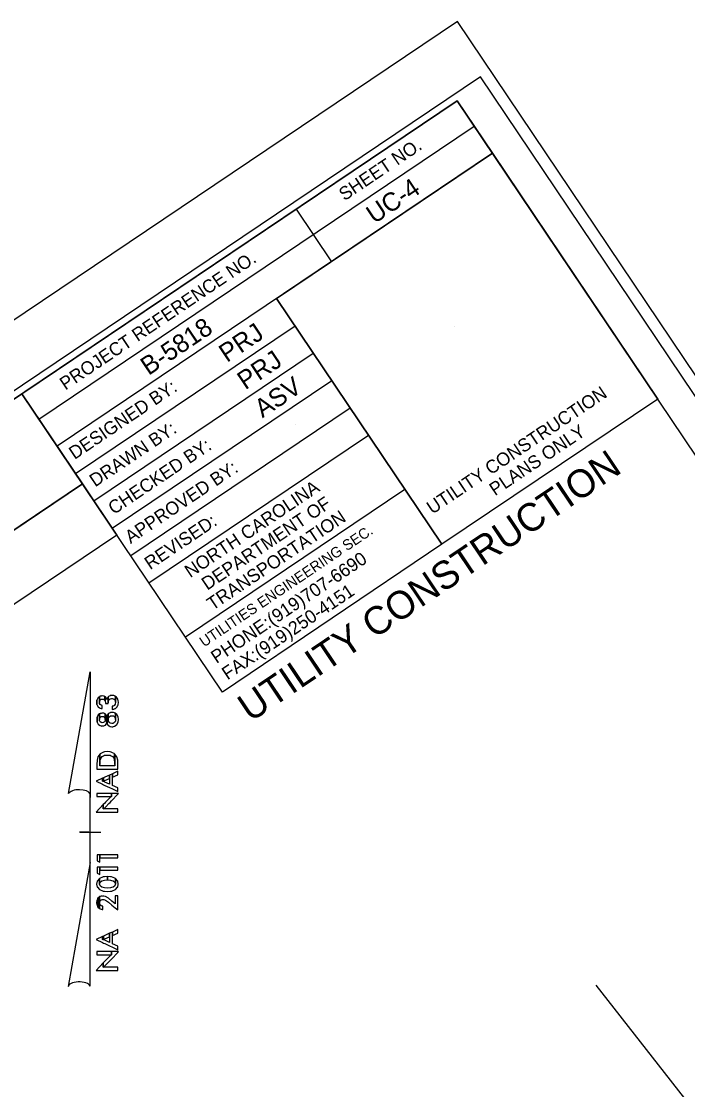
# Model space of a CAD drawing. Extents: x 1439200 to 1640973, y 392611 to 606444.
# Drawn here: x 1640660.5 to 1640762, y 393189.2 to 393351.9 of the extents above; entities that cross this region are included whole.
import ezdxf

# ---------------------------------------------------------------- set-up
doc = ezdxf.new("R2010")
doc.units = 0
for name, color, linetype in [('Matchline', 7, 'Continuous'), ('North Arrow NAD83 CELL', 7, 'Continuous'), ('Old_Level_60', 7, 'Continuous'), ('Sheet Data Field CELL', 7, 'Continuous'), ('Sheet Plot Border Inside CELL', 7, 'Continuous'), ('Sheet Plot Border Outside CELL', 7, 'Continuous'), ('Sheet Sticker Exception Certification CELL', 7, 'Continuous'), ('UC Plan Sheet 34 CELL', 7, 'Continuous')]:
    doc.layers.add(name, color=color, linetype=linetype)

msp = doc.modelspace()

# ---------------------------------------------------------------- linework, layer by layer
at = {"layer": 'Matchline'}
msp.add_line((1640747.99, 393205.15), (1640883.51, 393032.48), dxfattribs=at)
at = {"layer": 'North Arrow NAD83 CELL'}
for p, q in [((1640667.65, 393234.34), (1640670.94, 393252.88)), ((1640670.96, 393252.88), (1640670.94, 393252.88)), ((1640670.96, 393252.88), (1640670.94, 393252.88)), ((1640670.96, 393252.88), (1640670.95, 393233.76)), ((1640670.94, 393223.84), (1640670.95, 393234.32)), ((1640670.95, 393233.76), (1640670.95, 393234.3)), ((1640669.35, 393228.48), (1640669.33, 393228.48)), ((1640670.77, 393228.48), (1640669.35, 393228.48)), ((1640669.37, 393228.48), (1640672.57, 393228.48)), ((1640670.94, 393223.84), (1640667.6, 393204.94)), ((1640670.96, 393205.02), (1640670.94, 393223.84))]:
    msp.add_line(p, q, dxfattribs=at)
for points in [[(1640671.94, 393248.27), (1640671.98, 393247.9), (1640671.98, 393248.56)], [(1640672.74, 393247.29), (1640672.78, 393247.28), (1640672.78, 393247.75), (1640672.74, 393247.76), (1640672.63, 393247.78), (1640672.61, 393247.79), (1640672.61, 393247.79), (1640672.47, 393247.88), (1640672.47, 393247.89), (1640672.46, 393247.91), (1640672.39, 393248.03), (1640672.38, 393248.11), (1640672.37, 393248.14), (1640672.36, 393248.23), (1640672.36, 393249.09), (1640672.18, 393248.98), (1640672.14, 393248.89), (1640672.14, 393248.89), (1640672, 393248.65), (1640671.98, 393248.56), (1640671.98, 393247.9), (1640672, 393247.87), (1640672.14, 393247.59), (1640672.18, 393247.55), (1640672.36, 393247.4), (1640672.37, 393247.39), (1640672.38, 393247.39), (1640672.39, 393247.38), (1640672.46, 393247.36), (1640672.47, 393247.36), (1640672.47, 393247.35), (1640672.61, 393247.3), (1640672.61, 393247.3), (1640672.63, 393247.3)], [(1640673.1, 393248.62), (1640673.16, 393248.58), (1640673.16, 393249.12), (1640673.1, 393249.16), (1640673, 393249.18), (1640672.8, 393249.22), (1640672.79, 393249.22), (1640672.78, 393249.22), (1640672.74, 393249.21), (1640672.63, 393249.19), (1640672.61, 393249.19), (1640672.61, 393249.19), (1640672.61, 393249.19), (1640672.47, 393249.17), (1640672.47, 393249.16), (1640672.46, 393249.16), (1640672.39, 393249.12), (1640672.38, 393249.11), (1640672.37, 393249.1), (1640672.36, 393249.09), (1640672.36, 393248.23), (1640672.37, 393248.38), (1640672.38, 393248.42), (1640672.39, 393248.45), (1640672.46, 393248.57), (1640672.47, 393248.59), (1640672.47, 393248.59), (1640672.61, 393248.69), (1640672.61, 393248.69), (1640672.63, 393248.7), (1640672.74, 393248.72), (1640672.78, 393248.73), (1640672.79, 393248.73), (1640672.8, 393248.73), (1640673, 393248.69)], [(1640673.16, 393248.58), (1640673.24, 393248.41), (1640673.24, 393249.07), (1640673.16, 393249.12)], [(1640673.56, 393248.07), (1640673.68, 393248.07), (1640673.68, 393249.04), (1640673.55, 393248.87), (1640673.5, 393248.67), (1640673.45, 393248.82), (1640673.34, 393249.01), (1640673.27, 393249.06), (1640673.26, 393249.06), (1640673.24, 393249.07), (1640673.24, 393248.41), (1640673.26, 393248.22), (1640673.27, 393248.07), (1640673.34, 393248.07), (1640673.46, 393248.07), (1640673.5, 393248.07)], [(1640674.78, 393248.43), (1640674.81, 393248.26), (1640674.81, 393249.12), (1640674.78, 393249.14), (1640674.76, 393249.15), (1640674.76, 393249.15), (1640674.65, 393249.23), (1640674.64, 393249.23), (1640674.63, 393249.23), (1640674.55, 393249.25), (1640674.45, 393249.26), (1640674.44, 393249.27), (1640674.32, 393249.29), (1640674.22, 393249.28), (1640674.02, 393249.25), (1640673.99, 393249.24), (1640673.85, 393249.17), (1640673.74, 393249.11), (1640673.73, 393249.1), (1640673.69, 393249.05), (1640673.68, 393249.04), (1640673.68, 393248.17), (1640673.69, 393248.32), (1640673.73, 393248.49), (1640673.74, 393248.52), (1640673.85, 393248.68), (1640673.99, 393248.76), (1640674.02, 393248.78), (1640674.22, 393248.81), (1640674.32, 393248.8), (1640674.44, 393248.79), (1640674.45, 393248.78), (1640674.55, 393248.73), (1640674.63, 393248.69), (1640674.64, 393248.68), (1640674.65, 393248.66), (1640674.76, 393248.51)], [(1640675.2, 393247.87), (1640675.24, 393248.27), (1640675.2, 393248.46), (1640675.16, 393248.7), (1640675.05, 393248.88), (1640674.96, 393249.03), (1640674.82, 393249.12), (1640674.81, 393249.12), (1640674.81, 393248.26), (1640674.78, 393247.97), (1640674.76, 393247.95), (1640674.65, 393247.79), (1640674.64, 393247.76), (1640674.63, 393247.76), (1640674.55, 393247.72), (1640674.45, 393247.66), (1640674.44, 393247.66), (1640674.32, 393247.65), (1640674.31, 393247.65), (1640674.31, 393247.15), (1640674.32, 393247.16), (1640674.44, 393247.17), (1640674.45, 393247.17), (1640674.55, 393247.19), (1640674.63, 393247.22), (1640674.64, 393247.22), (1640674.65, 393247.23), (1640674.77, 393247.28), (1640674.78, 393247.28), (1640674.81, 393247.3), (1640674.82, 393247.3), (1640674.96, 393247.45), (1640675.05, 393247.54), (1640675.16, 393247.78)], [(1640673.39, 393244.92), (1640673.48, 393245.08), (1640673.48, 393246.13), (1640673.39, 393246.3), (1640673.39, 393246.3), (1640673.26, 393246.44), (1640673.26, 393246.44), (1640673.23, 393246.46), (1640673.23, 393245.6), (1640673.21, 393245.4), (1640673.11, 393245.25), (1640673.05, 393245.2), (1640673.05, 393245.2), (1640673.04, 393245.2), (1640672.97, 393245.16), (1640672.8, 393245.12), (1640672.74, 393245.14), (1640672.62, 393245.16), (1640672.47, 393245.27), (1640672.47, 393245.27), (1640672.42, 393245.35), (1640672.39, 393245.42), (1640672.36, 393245.61), (1640672.36, 393246.46), (1640672.17, 393246.31), (1640672, 393245.99), (1640672, 393245.22), (1640672.17, 393244.89), (1640672.36, 393244.75), (1640672.39, 393244.73), (1640672.42, 393244.7), (1640672.47, 393244.69), (1640672.47, 393244.69), (1640672.62, 393244.65), (1640672.74, 393244.62), (1640672.8, 393244.63), (1640672.97, 393244.65), (1640673.04, 393244.66), (1640673.05, 393244.66), (1640673.11, 393244.69), (1640673.21, 393244.74), (1640673.23, 393244.75), (1640673.26, 393244.77), (1640673.26, 393244.77), (1640673.39, 393244.92)], [(1640673.2, 393245.81), (1640673.23, 393245.6), (1640673.23, 393246.46), (1640673.2, 393246.47), (1640673.11, 393246.52), (1640673.05, 393246.56), (1640673.04, 393246.56), (1640672.97, 393246.56), (1640672.8, 393246.58), (1640672.8, 393246.58), (1640672.74, 393246.59), (1640672.62, 393246.55), (1640672.47, 393246.52), (1640672.47, 393246.51), (1640672.42, 393246.5), (1640672.39, 393246.47), (1640672.36, 393246.46), (1640672.36, 393245.61), (1640672.39, 393245.79), (1640672.42, 393245.86), (1640672.47, 393245.95), (1640672.47, 393245.95), (1640672.62, 393246.05), (1640672.74, 393246.07), (1640672.8, 393246.08), (1640672.97, 393246.05), (1640673.04, 393246.01), (1640673.05, 393246), (1640673.11, 393245.96)], [(1640675.19, 393245.21), (1640675.24, 393245.6), (1640675.19, 393246.01), (1640675.19, 393246.01), (1640675.03, 393246.36), (1640675.03, 393246.37), (1640674.82, 393246.53), (1640674.82, 393245.6), (1640674.79, 393245.36), (1640674.73, 393245.27), (1640674.73, 393245.26), (1640674.67, 393245.16), (1640674.49, 393245.05), (1640674.38, 393245.03), (1640674.37, 393245.03), (1640674.27, 393245.01), (1640674.04, 393245.05), (1640674.01, 393245.07), (1640673.85, 393245.19), (1640673.85, 393245.19), (1640673.74, 393245.38), (1640673.73, 393245.48), (1640673.72, 393245.54), (1640673.71, 393245.6), (1640673.71, 393246.49), (1640673.55, 393246.3), (1640673.55, 393244.91), (1640673.71, 393244.72), (1640673.72, 393244.71), (1640673.73, 393244.7), (1640673.74, 393244.69), (1640673.85, 393244.64), (1640673.85, 393244.64), (1640674.01, 393244.56), (1640674.04, 393244.55), (1640674.27, 393244.52), (1640674.37, 393244.51), (1640674.38, 393244.51), (1640674.49, 393244.54), (1640674.67, 393244.59), (1640674.73, 393244.61), (1640674.79, 393244.65), (1640674.82, 393244.68), (1640675.03, 393244.84), (1640675.03, 393244.85), (1640675.19, 393245.2)], [(1640674.79, 393245.85), (1640674.82, 393245.6), (1640674.82, 393246.53), (1640674.79, 393246.56), (1640674.73, 393246.6), (1640674.67, 393246.62), (1640674.49, 393246.66), (1640674.38, 393246.69), (1640674.37, 393246.7), (1640674.27, 393246.68), (1640674.27, 393246.68), (1640674.04, 393246.66), (1640674.01, 393246.65), (1640673.85, 393246.57), (1640673.85, 393246.56), (1640673.74, 393246.51), (1640673.72, 393246.5), (1640673.72, 393246.5), (1640673.71, 393246.49), (1640673.71, 393245.6), (1640673.72, 393245.67), (1640673.73, 393245.73), (1640673.74, 393245.83), (1640673.85, 393246.02), (1640673.85, 393246.02), (1640674.01, 393246.14), (1640674.04, 393246.16), (1640674.27, 393246.2), (1640674.37, 393246.18), (1640674.38, 393246.18), (1640674.49, 393246.16), (1640674.67, 393246.04), (1640674.73, 393245.94)], [(1640671.99, 393245.25), (1640672, 393245.22), (1640672, 393245.99), (1640671.99, 393245.99), (1640671.94, 393245.6), (1640671.94, 393245.6)], [(1640673.55, 393244.92), (1640673.55, 393244.91), (1640673.55, 393246.3), (1640673.54, 393246.29), (1640673.48, 393246.13), (1640673.48, 393245.08)], [(1640675.15, 393238.05), (1640675.16, 393238.05), (1640675.16, 393238.74), (1640675.15, 393239.4), (1640675.01, 393239.95), (1640674.69, 393240.35), (1640674.69, 393238.56), (1640674.68, 393238.56), (1640674.66, 393238.56), (1640674.59, 393238.56), (1640674.34, 393238.56), (1640674.16, 393238.56), (1640673.98, 393238.56), (1640673.57, 393238.56), (1640673.57, 393238.56), (1640673.15, 393238.56), (1640672.98, 393238.56), (1640672.79, 393238.56), (1640672.55, 393238.56), (1640672.48, 393238.56), (1640672.45, 393238.56), (1640672.44, 393238.56), (1640672.44, 393240.34), (1640672.13, 393239.95), (1640671.99, 393239.4), (1640671.98, 393238.74), (1640671.98, 393238.04), (1640671.99, 393238.04), (1640672.13, 393238.04), (1640672.44, 393238.04), (1640672.45, 393238.04), (1640672.48, 393238.04), (1640672.55, 393238.04), (1640672.79, 393238.04), (1640672.98, 393238.04), (1640673.15, 393238.04), (1640673.57, 393238.04), (1640673.57, 393238.04), (1640673.98, 393238.04), (1640674.16, 393238.04), (1640674.34, 393238.04), (1640674.59, 393238.04), (1640674.66, 393238.04), (1640674.68, 393238.04), (1640674.69, 393238.04), (1640675.01, 393238.05)], [(1640674.66, 393239.41), (1640674.68, 393239.34), (1640674.68, 393240.37), (1640674.66, 393240.39), (1640674.58, 393240.43), (1640674.34, 393240.56), (1640674.16, 393240.66), (1640673.98, 393240.69), (1640673.98, 393240.69), (1640673.57, 393240.74), (1640673.57, 393240.74), (1640673.15, 393240.69), (1640672.98, 393240.66), (1640672.79, 393240.56), (1640672.55, 393240.43), (1640672.48, 393240.39), (1640672.45, 393240.36), (1640672.44, 393240.34), (1640672.44, 393238.75), (1640672.45, 393239.34), (1640672.48, 393239.43), (1640672.55, 393239.69), (1640672.79, 393239.98), (1640672.98, 393240.07), (1640673.15, 393240.16), (1640673.57, 393240.21), (1640673.57, 393240.21), (1640673.98, 393240.16), (1640674.16, 393240.07), (1640674.34, 393239.98), (1640674.58, 393239.69)], [(1640674.68, 393239.34), (1640674.69, 393238.75), (1640674.69, 393240.35), (1640674.68, 393240.37)], [(1640674.34, 393235.05), (1640675.16, 393234.67), (1640675.16, 393235.21), (1640674.34, 393235.58), (1640674.34, 393237.36), (1640673.91, 393237.16), (1640673.91, 393235.77), (1640673.19, 393236.09), (1640673.18, 393236.1), (1640673, 393236.16), (1640673, 393236.16), (1640672.82, 393236.21), (1640672.82, 393236.66), (1640671.85, 393236.2), (1640672.82, 393235.75), (1640673, 393235.67), (1640673, 393235.67), (1640673.18, 393235.59), (1640673.19, 393235.58), (1640673.91, 393235.25)], [(1640672.82, 393236.21), (1640673, 393236.26), (1640673, 393236.74), (1640672.82, 393236.66)], [(1640673.19, 393236.33), (1640673.91, 393236.65), (1640673.91, 393237.16), (1640673.18, 393236.82), (1640673.18, 393236.82), (1640673, 393236.74), (1640673, 393236.74), (1640673, 393236.26), (1640673, 393236.26), (1640673.18, 393236.33)], [(1640674.34, 393236.84), (1640675.16, 393237.2), (1640675.16, 393237.75), (1640674.34, 393237.36)], [(1640673.98, 393233.89), (1640674.19, 393233.89), (1640674.19, 393234.37), (1640673.98, 393234.37), (1640673.8, 393234.37), (1640673.3, 393234.37), (1640673.11, 393234.37), (1640671.98, 393234.36), (1640671.98, 393233.89), (1640673.11, 393233.89), (1640673.3, 393233.89), (1640673.8, 393233.89)], [(1640675.16, 393234.24), (1640675.29, 393234.37), (1640675.16, 393234.37), (1640674.19, 393234.37), (1640674.19, 393233.89), (1640673.98, 393233.72), (1640673.8, 393233.54), (1640673.3, 393233.03), (1640673.11, 393232.83), (1640672.95, 393232.66), (1640672.95, 393232), (1640673.11, 393232.12), (1640673.31, 393232.3), (1640673.8, 393232.82), (1640673.98, 393233), (1640674.19, 393233.22)], [(1640674.19, 393231.52), (1640675.16, 393231.52), (1640675.16, 393232), (1640674.19, 393232), (1640673.98, 393232), (1640673.8, 393232), (1640673.31, 393232), (1640673.11, 393232), (1640672.95, 393232), (1640672.95, 393232.66), (1640671.86, 393231.52), (1640672.95, 393231.52), (1640673.12, 393231.52), (1640673.31, 393231.52), (1640673.8, 393231.52), (1640673.98, 393231.52)], [(1640671.99, 393224.08), (1640672.41, 393223.88), (1640672.41, 393225.01), (1640671.99, 393225.01)], [(1640672.41, 393224.53), (1640675.15, 393224.53), (1640675.15, 393225.01), (1640672.41, 393225.01)], [(1640671.99, 393222.2), (1640672.41, 393222), (1640672.41, 393223.13), (1640671.99, 393223.13)], [(1640672.41, 393222.66), (1640675.15, 393222.66), (1640675.15, 393223.13), (1640672.41, 393223.13)], [(1640675.14, 393220.1), (1640675.23, 393220.55), (1640675.14, 393220.99), (1640675.13, 393221.02), (1640674.79, 393221.39), (1640674.79, 393220.54), (1640674.78, 393220.52), (1640674.78, 393220.51), (1640674.71, 393220.27), (1640674.46, 393220.07), (1640674.45, 393220.07), (1640674.45, 393220.07), (1640674.22, 393220.01), (1640674.22, 393220.01), (1640674.06, 393219.96), (1640674.05, 393219.96), (1640673.59, 393219.92), (1640673.58, 393219.92), (1640673.58, 393219.92), (1640673.12, 393219.96), (1640672.95, 393220.01), (1640672.94, 393220.01), (1640672.72, 393220.07), (1640672.71, 393220.07), (1640672.45, 393220.27), (1640672.38, 393220.53), (1640672.38, 393220.54), (1640672.38, 393220.56), (1640672.38, 393221.4), (1640672.04, 393221.03), (1640672.03, 393221.01), (1640671.93, 393220.55), (1640671.93, 393220.55), (1640672.03, 393220.08), (1640672.04, 393220.08), (1640672.38, 393219.71), (1640672.38, 393219.7), (1640672.38, 393219.7), (1640672.45, 393219.68), (1640672.71, 393219.57), (1640672.72, 393219.57), (1640672.94, 393219.47), (1640672.95, 393219.47), (1640673.12, 393219.46), (1640673.58, 393219.41), (1640673.58, 393219.41), (1640673.59, 393219.41), (1640674.05, 393219.45), (1640674.06, 393219.45), (1640674.22, 393219.47), (1640674.23, 393219.47), (1640674.45, 393219.57), (1640674.46, 393219.57), (1640674.71, 393219.67), (1640674.78, 393219.7), (1640674.78, 393219.7), (1640674.79, 393219.71), (1640675.13, 393220.09)], [(1640673.12, 393221.14), (1640673.58, 393221.18), (1640673.58, 393221.69), (1640673.12, 393221.65), (1640672.94, 393221.63), (1640672.94, 393221.63), (1640672.94, 393221.63), (1640672.72, 393221.54), (1640672.72, 393221.54), (1640672.71, 393221.54), (1640672.45, 393221.43), (1640672.45, 393221.43), (1640672.38, 393221.41), (1640672.38, 393221.4), (1640672.38, 393221.4), (1640672.38, 393220.56), (1640672.38, 393220.58), (1640672.38, 393220.59), (1640672.45, 393220.83), (1640672.71, 393221.03), (1640672.72, 393221.03), (1640672.94, 393221.09), (1640672.94, 393221.09)], [(1640674.78, 393220.57), (1640674.79, 393220.54), (1640674.79, 393221.39), (1640674.78, 393221.4), (1640674.78, 393221.4), (1640674.71, 393221.43), (1640674.46, 393221.53), (1640674.45, 393221.54), (1640674.22, 393221.63), (1640674.22, 393221.63), (1640674.06, 393221.65), (1640674.04, 393221.65), (1640673.59, 393221.69), (1640673.58, 393221.69), (1640673.58, 393221.69), (1640673.58, 393221.18), (1640673.58, 393221.18), (1640673.59, 393221.18), (1640674.05, 393221.14), (1640674.06, 393221.14), (1640674.22, 393221.1), (1640674.22, 393221.1), (1640674.45, 393221.03), (1640674.46, 393221.03), (1640674.71, 393220.83), (1640674.78, 393220.58)], [(1640672.12, 393217.06), (1640672.13, 393217.05), (1640672.13, 393218.41), (1640672.12, 393218.41), (1640671.99, 393218.11), (1640671.97, 393218.07), (1640671.93, 393217.7), (1640671.93, 393217.7), (1640671.97, 393217.45), (1640671.99, 393217.34)], [(1640672.13, 393217.05), (1640672.36, 393216.83), (1640672.36, 393218.61), (1640672.13, 393218.41)], [(1640672.82, 393216.69), (1640672.87, 393216.69), (1640672.87, 393217.18), (1640672.82, 393217.19), (1640672.79, 393217.19), (1640672.79, 393217.19), (1640672.65, 393217.24), (1640672.63, 393217.25), (1640672.61, 393217.27), (1640672.49, 393217.36), (1640672.46, 393217.42), (1640672.4, 393217.54), (1640672.4, 393217.56), (1640672.39, 393217.8), (1640672.39, 393218.64), (1640672.36, 393218.61), (1640672.36, 393216.83), (1640672.39, 393216.82), (1640672.4, 393216.81), (1640672.4, 393216.81), (1640672.46, 393216.78), (1640672.49, 393216.77), (1640672.61, 393216.72), (1640672.63, 393216.71), (1640672.65, 393216.71), (1640672.79, 393216.7), (1640672.79, 393216.69)], [(1640674.74, 393216.95), (1640675.15, 393216.61), (1640675.15, 393218.74), (1640674.74, 393218.74), (1640674.74, 393217.53), (1640674.27, 393217.94), (1640673.72, 393218.38), (1640673.72, 393218.39), (1640673.29, 393218.64), (1640673.29, 393218.64), (1640673.28, 393218.65), (1640673.01, 393218.7), (1640672.87, 393218.73), (1640672.82, 393218.74), (1640672.79, 393218.73), (1640672.79, 393218.73), (1640672.65, 393218.7), (1640672.63, 393218.7), (1640672.61, 393218.69), (1640672.49, 393218.67), (1640672.49, 393218.67), (1640672.46, 393218.66), (1640672.4, 393218.65), (1640672.4, 393218.65), (1640672.39, 393218.64), (1640672.39, 393217.8), (1640672.4, 393217.83), (1640672.4, 393217.85), (1640672.46, 393218.02), (1640672.49, 393218.05), (1640672.61, 393218.16), (1640672.63, 393218.17), (1640672.65, 393218.17), (1640672.79, 393218.22), (1640672.79, 393218.22), (1640672.82, 393218.22), (1640672.87, 393218.22), (1640673.01, 393218.21), (1640673.28, 393218.11), (1640673.29, 393218.1), (1640673.72, 393217.8), (1640673.72, 393217.8), (1640674.27, 393217.34)], [(1640674.33, 393210.94), (1640675.15, 393210.56), (1640675.15, 393211.1), (1640674.33, 393211.47), (1640674.33, 393213.25), (1640673.9, 393213.05), (1640673.9, 393211.66), (1640673.18, 393211.99), (1640673.17, 393211.99), (1640672.99, 393212.05), (1640672.99, 393212.05), (1640672.81, 393212.1), (1640672.81, 393212.55), (1640671.84, 393212.1), (1640672.81, 393211.64), (1640672.99, 393211.56), (1640672.99, 393211.56), (1640673.17, 393211.48), (1640673.18, 393211.48), (1640673.9, 393211.14)], [(1640672.81, 393212.1), (1640672.99, 393212.15), (1640672.99, 393212.63), (1640672.81, 393212.55)], [(1640673.18, 393212.22), (1640673.9, 393212.54), (1640673.9, 393213.05), (1640673.17, 393212.72), (1640673.17, 393212.72), (1640672.99, 393212.63), (1640672.99, 393212.63), (1640672.99, 393212.15), (1640672.99, 393212.16), (1640673.17, 393212.22)], [(1640674.33, 393212.73), (1640675.15, 393213.09), (1640675.15, 393213.64), (1640674.33, 393213.25)], [(1640673.97, 393209.78), (1640674.18, 393209.78), (1640674.18, 393210.26), (1640673.97, 393210.26), (1640673.79, 393210.26), (1640673.29, 393210.26), (1640673.1, 393210.26), (1640671.97, 393210.26), (1640671.97, 393209.78), (1640673.1, 393209.78), (1640673.29, 393209.78), (1640673.79, 393209.78)], [(1640675.15, 393210.13), (1640675.28, 393210.26), (1640675.15, 393210.26), (1640674.18, 393210.26), (1640674.18, 393209.78), (1640673.97, 393209.61), (1640673.79, 393209.43), (1640673.3, 393208.92), (1640673.1, 393208.72), (1640672.94, 393208.55), (1640672.94, 393207.89), (1640673.1, 393208.01), (1640673.3, 393208.19), (1640673.79, 393208.71), (1640673.97, 393208.9), (1640674.18, 393209.11)], [(1640674.18, 393207.41), (1640675.15, 393207.41), (1640675.15, 393207.89), (1640674.18, 393207.89), (1640673.97, 393207.89), (1640673.79, 393207.89), (1640673.3, 393207.89), (1640673.1, 393207.89), (1640672.94, 393207.89), (1640672.94, 393208.55), (1640671.85, 393207.41), (1640672.94, 393207.41), (1640673.11, 393207.41), (1640673.3, 393207.41), (1640673.79, 393207.41), (1640673.97, 393207.41)]]:
    msp.add_lwpolyline(points, close=True, dxfattribs=at)
for centre, start_param, end_param in [((1640669.3, 393234.14), 0.216388, 2.908219), ((1640669.29, 393204.87), 0.201328, 3.141593)]:
    msp.add_ellipse(centre, major_axis=(1.69, -0.01), ratio=0.461098, start_param=start_param, end_param=end_param, dxfattribs=at)
at = {"layer": 'Old_Level_60'}
msp.add_lwpolyline([(1640594.15, 393250.57), (1640660.54, 393295.23), (1640669.78, 393281.5), (1640603.39, 393236.83)], close=True, dxfattribs=at)
at = {"layer": 'Sheet Plot Border Inside CELL'}
msp.add_lwpolyline([(1640730.44, 393343.49), (1640177.37, 392971.37), (1640412.97, 392621.21), (1640966.04, 392993.34)], close=True, dxfattribs=at)
at = {"layer": 'Sheet Plot Border Outside CELL'}
msp.add_lwpolyline([(1640726.92, 393351.95), (1640168.05, 392975.92), (1640413.67, 392610.86), (1640972.54, 392986.89)], close=True, dxfattribs=at)
at = {"layer": 'Sheet Sticker Exception Certification CELL'}
for p, q in [((1640603.39, 393236.83), (1640669.78, 393281.5)), ((1640669.78, 393281.49), (1640675.03, 393273.7)), ((1640675.03, 393273.7), (1640608.64, 393229.03))]:
    msp.add_line(p, q, dxfattribs=at)
at = {"layer": 'UC Plan Sheet 34 CELL'}
for p, q in [((1640663.13, 393291.38), (1640729.45, 393336.01)), ((1640718.55, 393325.66), (1640718.55, 393325.66)), ((1640702.33, 393323.35), (1640707.71, 393315.34)), ((1640668.72, 393283.07), (1640702.16, 393305.56)), ((1640726.45, 393305.53), (1640726.45, 393305.53)), ((1640685.41, 393303.37), (1640685.41, 393303.37)), ((1640693.91, 393303.03), (1640693.91, 393303.03)), ((1640671.52, 393278.91), (1640704.95, 393301.4)), ((1640696.71, 393298.87), (1640696.71, 393298.87)), ((1640674.32, 393274.75), (1640707.75, 393297.25)), ((1640699.5, 393294.72), (1640699.5, 393294.72)), ((1640677.12, 393270.6), (1640710.55, 393293.09)), ((1640702.3, 393290.56), (1640702.3, 393290.56)), ((1640679.91, 393266.44), (1640713.35, 393288.93)), ((1640685.46, 393258.19), (1640718.9, 393280.68))]:
    msp.add_line(p, q, dxfattribs=at)
msp.add_lwpolyline([(1640726.86, 393339.86), (1640229.05, 393004.91), (1640463.51, 392656.45), (1640961.32, 392991.39)], close=True, dxfattribs=at)
for points in [[(1640660.54, 393295.23), (1640726.86, 393339.86), (1640732.23, 393331.87)], [(1640732.23, 393331.87), (1640665.91, 393287.24), (1640660.54, 393295.23)], [(1640757.43, 393294.43), (1640724.54, 393272.3), (1640699.36, 393309.72), (1640732.25, 393331.85)], [(1640732.25, 393331.85), (1640757.43, 393294.43)], [(1640699.35, 393309.74), (1640724.54, 393272.3), (1640691.1, 393249.8), (1640660.54, 393295.23)]]:
    msp.add_lwpolyline(points, dxfattribs=at)

# ---------------------------------------------------------------- texts
at = {"layer": 'Sheet Data Field CELL'}
for s, p in [('UC-4', (1640714.23, 393321.03)), ('B-5818', (1640679.84, 393297.94)), ('PRJ', (1640691.78, 393299.91)), ('PRJ', (1640694.58, 393295.75)), ('ASV', (1640697.2, 393291.48))]:
    msp.add_text(s, height=2.8, rotation=33.9342, dxfattribs=at).set_placement(p)
at = {"layer": 'UC Plan Sheet 34 CELL'}
for s, height, p in [('SHEET NO.', 2.005, (1640709.7, 393324.54)), ('PROJECT REFERENCE NO.', 2.0046, (1640667.17, 393295.7)), ('DESIGNED BY:', 2.0046, (1640668.57, 393285.14)), ('UTILITY CONSTRUCTION', 2.0046, (1640723.08, 393276.81)), ('DRAWN BY:', 2.005, (1640671.7, 393280.96)), ('PLANS ONLY', 2.005, (1640732.63, 393279.61)), ('CHECKED BY:', 2.0046, (1640674.55, 393276.75)), ('UTILITY CONSTRUCTION', 4.25, (1640695.34, 393245.12)), ('APPROVED BY:', 2.0046, (1640677.11, 393272.33)), ('NORTH CAROLINA', 2.0046, (1640686.2, 393267.12)), ('DEPARTMENT OF', 2.0046, (1640688.78, 393265.23)), ('TRANSPORTATION', 2.0046, (1640689.6, 393262.15)), ('REVISED:', 2.005, (1640680.08, 393268.36)), ('UTILITIES ENGINEERING SEC.', 1.6037, (1640688.3, 393256.59)), ('PHONE:(919)707-6690', 2.0046, (1640690.2, 393254.07)), ('FAX:(919)250-4151', 2.0046, (1640691.87, 393251.57))]:
    msp.add_text(s, height=height, rotation=33.9342, dxfattribs=at).set_placement(p)

doc.saveas('drawing.dxf')
